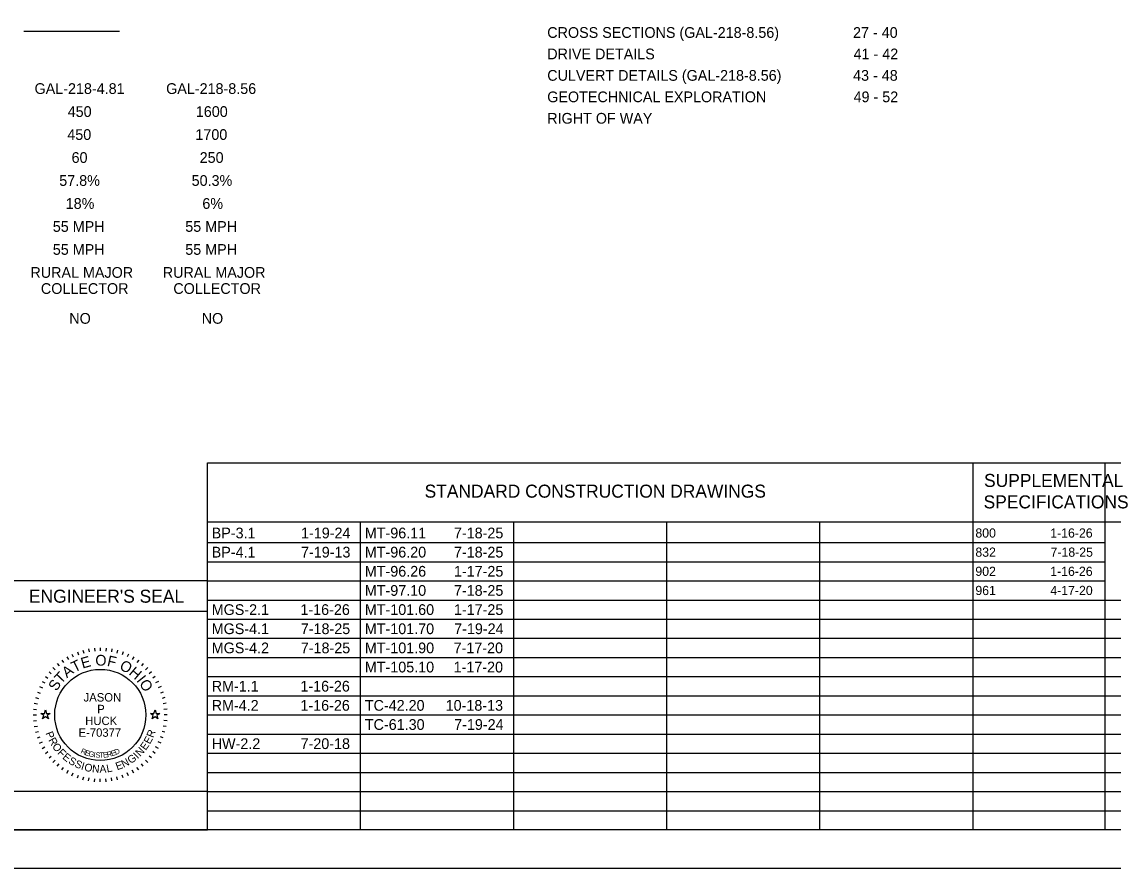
# Model space of a CAD drawing. Extents: x 0 to 34, y 0 to 22.
# Drawn here: x 7.72 to 21.98, y 0 to 11.05 of the extents above; entities that cross this region are included whole.
import ezdxf

# ---------------------------------------------------------------- set-up
doc = ezdxf.new("R2010")
doc.units = 0
for name, color, linetype in [('Default', 7, 'Continuous'), ('SH_Border', 7, 'Continuous'), ('SH_Cut_Line', 7, 'Continuous'), ('SH_Data', 7, 'Continuous'), ('SH_Text', 7, 'Continuous')]:
    doc.layers.add(name, color=color, linetype=linetype)

msp = doc.modelspace()

# ---------------------------------------------------------------- linework, layer by layer
at = {"layer": 'Default'}
for points in [[(7.974, 2.02), (8.021, 2.02), (8.035, 2.065), (8.049, 2.02), (8.096, 2.02), (8.058, 1.992), (8.073, 1.948), (8.035, 1.975), (7.997, 1.948), (8.012, 1.992)], [(9.404, 2.02), (9.451, 2.02), (9.465, 2.065), (9.479, 2.02), (9.526, 2.02), (9.488, 1.992), (9.503, 1.948), (9.465, 1.975), (9.427, 1.948), (9.442, 1.992)]]:
    msp.add_lwpolyline(points, close=True, dxfattribs=at)
at = {"layer": 'SH_Border'}
msp.add_lwpolyline([(1.5, 21.5), (33.5, 21.5), (33.5, 0.5), (1.5, 0.5)], close=True, dxfattribs=at)
at = {"layer": 'SH_Cut_Line'}
msp.add_lwpolyline([(0, 0), (34, 0), (34, 22), (0, 22)], close=True, dxfattribs=at)
at = {"layer": 'SH_Data'}
for p, q in [((9, 10.922), (7.75, 10.922)), ((10.15, 5.292), (23.6, 5.292)), ((10.15, 0.5), (10.15, 5.292)), ((20.15, 0.5), (20.15, 5.292)), ((21.875, 0.5), (21.875, 5.292)), ((10.15, 4.521), (23.6, 4.521)), ((12.15, 0.5), (12.15, 4.521)), ((14.15, 0.5), (14.15, 4.521)), ((16.15, 0.5), (16.15, 4.521)), ((18.15, 0.5), (18.15, 4.521)), ((10.15, 4.25), (21.875, 4.25)), ((10.15, 4), (21.875, 4)), ((10.15, 3.75), (7.35, 3.75)), ((10.15, 3.75), (21.875, 3.75)), ((10.15, 0.5), (10.15, 3.75)), ((10.15, 3.5), (23.6, 3.5)), ((10.15, 3.35), (7.35, 3.35)), ((10.15, 3.25), (23.6, 3.25)), ((10.15, 3), (23.6, 3)), ((8.598, 2.862), (8.605, 2.822)), ((8.674, 2.872), (8.677, 2.832)), ((8.75, 2.875), (8.75, 2.835)), ((8.826, 2.872), (8.823, 2.832)), ((8.902, 2.862), (8.895, 2.822)), ((8.248, 2.717), (8.271, 2.684)), ((8.313, 2.758), (8.333, 2.723)), ((8.38, 2.793), (8.397, 2.757)), ((8.451, 2.822), (8.464, 2.785)), ((8.524, 2.845), (8.534, 2.807)), ((8.976, 2.845), (8.966, 2.807)), ((9.049, 2.822), (9.036, 2.785)), ((9.12, 2.793), (9.103, 2.757)), ((9.187, 2.758), (9.167, 2.723)), ((9.252, 2.717), (9.229, 2.684)), ((10.15, 2.75), (23.6, 2.75)), ((8.131, 2.619), (8.16, 2.59)), ((8.188, 2.67), (8.213, 2.64)), ((9.312, 2.67), (9.287, 2.64)), ((9.369, 2.619), (9.34, 2.59)), ((7.992, 2.438), (8.027, 2.418)), ((8.033, 2.502), (8.066, 2.479)), ((8.08, 2.562), (8.11, 2.537)), ((9.42, 2.562), (9.39, 2.537)), ((9.467, 2.502), (9.434, 2.479)), ((9.508, 2.438), (9.473, 2.418)), ((10.15, 2.5), (23.6, 2.5)), ((7.928, 2.299), (7.965, 2.286)), ((7.957, 2.37), (7.993, 2.353)), ((9.543, 2.37), (9.507, 2.353)), ((9.572, 2.299), (9.535, 2.286)), ((7.888, 2.152), (7.928, 2.145)), ((7.905, 2.226), (7.943, 2.216)), ((9.595, 2.226), (9.557, 2.216)), ((9.612, 2.152), (9.572, 2.145)), ((10.15, 2.25), (23.6, 2.25)), ((7.875, 2), (7.915, 2)), ((7.878, 2.076), (7.918, 2.073)), ((9.622, 2.076), (9.582, 2.073)), ((9.625, 2), (9.585, 2)), ((10.15, 2), (23.6, 2)), ((7.878, 1.924), (7.918, 1.927)), ((7.888, 1.848), (7.928, 1.855)), ((9.612, 1.848), (9.572, 1.855)), ((9.622, 1.924), (9.582, 1.927)), ((7.905, 1.774), (7.943, 1.784)), ((7.928, 1.701), (7.965, 1.714)), ((9.572, 1.701), (9.535, 1.714)), ((9.595, 1.774), (9.557, 1.784)), ((10.15, 1.75), (23.6, 1.75)), ((7.957, 1.63), (7.993, 1.647)), ((7.992, 1.563), (8.027, 1.583)), ((9.508, 1.563), (9.473, 1.583)), ((9.543, 1.63), (9.507, 1.647)), ((8.033, 1.498), (8.066, 1.521)), ((8.08, 1.438), (8.11, 1.463)), ((9.42, 1.438), (9.39, 1.463)), ((9.467, 1.498), (9.434, 1.521)), ((10.15, 1.5), (23.6, 1.5)), ((8.131, 1.381), (8.16, 1.41)), ((8.188, 1.33), (8.213, 1.36)), ((8.248, 1.283), (8.271, 1.316)), ((9.252, 1.283), (9.229, 1.316)), ((9.312, 1.33), (9.287, 1.36)), ((9.369, 1.381), (9.34, 1.41)), ((8.313, 1.242), (8.333, 1.277)), ((8.38, 1.207), (8.397, 1.243)), ((8.451, 1.178), (8.464, 1.215)), ((8.524, 1.155), (8.534, 1.193)), ((8.598, 1.138), (8.605, 1.178)), ((8.674, 1.128), (8.677, 1.168)), ((8.75, 1.125), (8.75, 1.165)), ((8.826, 1.128), (8.823, 1.168)), ((8.902, 1.138), (8.895, 1.178)), ((8.976, 1.155), (8.966, 1.193)), ((9.049, 1.178), (9.036, 1.215)), ((9.12, 1.207), (9.103, 1.243)), ((9.187, 1.242), (9.167, 1.277)), ((10.15, 1.25), (23.6, 1.25)), ((10.15, 1), (23.6, 1)), ((10.15, 0.75), (23.6, 0.75)), ((10.15, 0.5), (7.35, 0.5))]:
    msp.add_line(p, q, dxfattribs=at)
msp.add_lwpolyline([(10.15, 0.5), (10.15, 1), (7.35, 1), (7.35, 0.5)], close=True, dxfattribs=at)
msp.add_circle((8.75, 2), 0.595, dxfattribs=at)

# ---------------------------------------------------------------- texts
for s, height, p in [("ENGINEER'S SEAL", 0.17, (7.818, 3.465)), ('JASON', 0.11, (8.532, 2.175)), ('P', 0.11, (8.71, 2.022)), ('HUCK', 0.11, (8.553, 1.868)), ('E-70377', 0.11, (8.466, 1.715))]:
    msp.add_text(s, height=height, dxfattribs=at).set_placement(p)
for s, height, rotation, p in [('T', 0.14, 25.7167, (8.412, 2.552)), ('E', 0.14, 15.7571, (8.518, 2.604)), ('O', 0.14, 359.7812, (8.685, 2.644)), ('F', 0.14, 347.4362, (8.831, 2.642)), ('T', 0.14, 46.4344, (8.238, 2.396)), ('A', 0.14, 36.4747, (8.313, 2.478)), ('O', 0.14, 332.2586, (8.99, 2.602)), ('H', 0.14, 319.9136, (9.113, 2.536)), ('S', 0.14, 57.1924, (8.178, 2.301)), ('I', 0.14, 308.367, (9.216, 2.448)), ('O', 0.14, 303.1491, (9.252, 2.409)), ('P', 0.1, 291.494, (8.032, 1.762)), ('E', 0.1, 61.9951, (9.398, 1.61)), ('R', 0.1, 69.2322, (9.442, 1.695)), ('R', 0.1, 298.7311, (8.069, 1.672)), ('O', 0.1, 306.4666, (8.115, 1.588)), ('N', 0.1, 47.0224, (9.27, 1.451)), ('E', 0.1, 54.758, (9.343, 1.531)), ('F', 0.1, 314.7068, (8.184, 1.498)), ('E', 0.1, 321.4393, (8.248, 1.435)), ('S', 0.1, 328.6764, (8.324, 1.375)), ('R', 0.07, 334.487, (8.487, 1.505)), ('E', 0.07, 341.04, (8.541, 1.48)), ('G', 0.07, 347.4752, (8.591, 1.462)), ('I', 0.07, 353.7858, (8.659, 1.447)), ('S', 0.07, 356.8926, (8.686, 1.443)), ('T', 0.07, 3.0061, (8.736, 1.439)), ('E', 0.07, 6.0117, (8.789, 1.441)), ('R', 0.07, 11.9184, (8.842, 1.447)), ('E', 0.07, 17.6836, (8.9, 1.46)), ('D', 0.07, 23.3052, (8.951, 1.477)), ('N', 0.1, 27.3113, (9.054, 1.308)), ('G', 0.1, 35.0469, (9.148, 1.357)), ('I', 0.1, 43.287, (9.237, 1.421)), ('S', 0.1, 335.9134, (8.406, 1.327)), ('I', 0.1, 343.1505, (8.491, 1.29)), ('O', 0.1, 346.8859, (8.534, 1.275)), ('N', 0.1, 355.1261, (8.639, 1.252)), ('A', 0.1, 2.8617, (8.742, 1.244)), ('L', 0.1, 10.0987, (8.839, 1.249)), ('E', 0.1, 20.0742, (8.971, 1.277))]:
    msp.add_text(s, height=height, rotation=rotation, dxfattribs=at).set_placement(p)
at = {"layer": 'SH_Text'}
for s, height, p in [('CROSS SECTIONS (GAL-218-8.56)', 0.14, (14.588, 10.838)), ('27 - 40', 0.14, (18.582, 10.838)), ('DRIVE DETAILS', 0.14, (14.588, 10.558)), ('41 - 42', 0.14, (18.589, 10.558)), ('CULVERT DETAILS (GAL-218-8.56)', 0.14, (14.588, 10.278)), ('43 - 48', 0.14, (18.583, 10.278)), ('GAL-218-4.81', 0.14, (7.891, 10.106)), ('GAL-218-8.56', 0.14, (9.61, 10.106)), ('GEOTECHNICAL EXPLORATION', 0.14, (14.588, 9.998)), ('49 - 52', 0.14, (18.589, 9.998)), ('450', 0.14, (8.324, 9.806)), ('1600', 0.14, (9.998, 9.806)), ('RIGHT OF WAY', 0.14, (14.588, 9.718)), ('450', 0.14, (8.319, 9.506)), ('1700', 0.14, (9.992, 9.506)), ('60', 0.14, (8.375, 9.206)), ('250', 0.14, (10.048, 9.206)), ('57.8%', 0.14, (8.214, 8.906)), ('50.3%', 0.14, (9.943, 8.906)), ('18%', 0.14, (8.298, 8.606)), ('6%', 0.14, (10.083, 8.606)), ('55 MPH', 0.14, (8.13, 8.306)), ('55 MPH', 0.14, (9.86, 8.306)), ('55 MPH', 0.14, (8.13, 8.006)), ('55 MPH', 0.14, (9.86, 8.006)), ('RURAL MAJOR', 0.14, (7.837, 7.706)), ('RURAL MAJOR', 0.14, (9.566, 7.706)), ('COLLECTOR', 0.14, (7.974, 7.496)), ('COLLECTOR', 0.14, (9.704, 7.496)), ('NO', 0.14, (8.345, 7.106)), ('NO', 0.14, (10.075, 7.106)), ('SUPPLEMENTAL', 0.17, (20.293, 4.976)), ('STANDARD CONSTRUCTION DRAWINGS', 0.17, (12.986, 4.836)), ('SPECIFICATIONS', 0.17, (20.287, 4.696)), ('BP-3.1', 0.14, (10.205, 4.305)), ('1-19-24', 0.14, (11.372, 4.305)), ('MT-96.11', 0.14, (12.205, 4.305)), ('7-18-25', 0.14, (13.369, 4.305)), ('800', 0.12, (20.18, 4.315)), ('1-16-26', 0.12, (21.158, 4.315)), ('BP-4.1', 0.14, (10.205, 4.055)), ('7-19-13', 0.14, (11.372, 4.055)), ('MT-96.20', 0.14, (12.205, 4.055)), ('7-18-25', 0.14, (13.369, 4.055)), ('832', 0.12, (20.18, 4.065)), ('7-18-25', 0.12, (21.162, 4.065)), ('MT-96.26', 0.14, (12.205, 3.805)), ('1-17-25', 0.14, (13.369, 3.805)), ('902', 0.12, (20.18, 3.815)), ('1-16-26', 0.12, (21.158, 3.815)), ('MT-97.10', 0.14, (12.205, 3.555)), ('7-18-25', 0.14, (13.369, 3.555)), ('961', 0.12, (20.18, 3.565)), ('4-17-20', 0.12, (21.159, 3.565)), ('MGS-2.1', 0.14, (10.205, 3.305)), ('1-16-26', 0.14, (11.364, 3.305)), ('MT-101.60', 0.14, (12.205, 3.305)), ('1-17-25', 0.14, (13.369, 3.305)), ('MGS-4.1', 0.14, (10.205, 3.055)), ('7-18-25', 0.14, (11.369, 3.055)), ('MT-101.70', 0.14, (12.205, 3.055)), ('7-19-24', 0.14, (13.372, 3.055)), ('MGS-4.2', 0.14, (10.205, 2.805)), ('7-18-25', 0.14, (11.369, 2.805)), ('MT-101.90', 0.14, (12.205, 2.805)), ('7-17-20', 0.14, (13.365, 2.805)), ('MT-105.10', 0.14, (12.205, 2.555)), ('1-17-20', 0.14, (13.365, 2.555)), ('RM-1.1', 0.14, (10.205, 2.305)), ('1-16-26', 0.14, (11.364, 2.305)), ('RM-4.2', 0.14, (10.205, 2.055)), ('1-16-26', 0.14, (11.364, 2.055)), ('TC-42.20', 0.14, (12.205, 2.055)), ('10-18-13', 0.14, (13.261, 2.055)), ('TC-61.30', 0.14, (12.205, 1.805)), ('7-19-24', 0.14, (13.372, 1.805)), ('HW-2.2', 0.14, (10.205, 1.555)), ('7-20-18', 0.14, (11.366, 1.555))]:
    msp.add_text(s, height=height, dxfattribs=at).set_placement(p)

doc.saveas('drawing.dxf')
